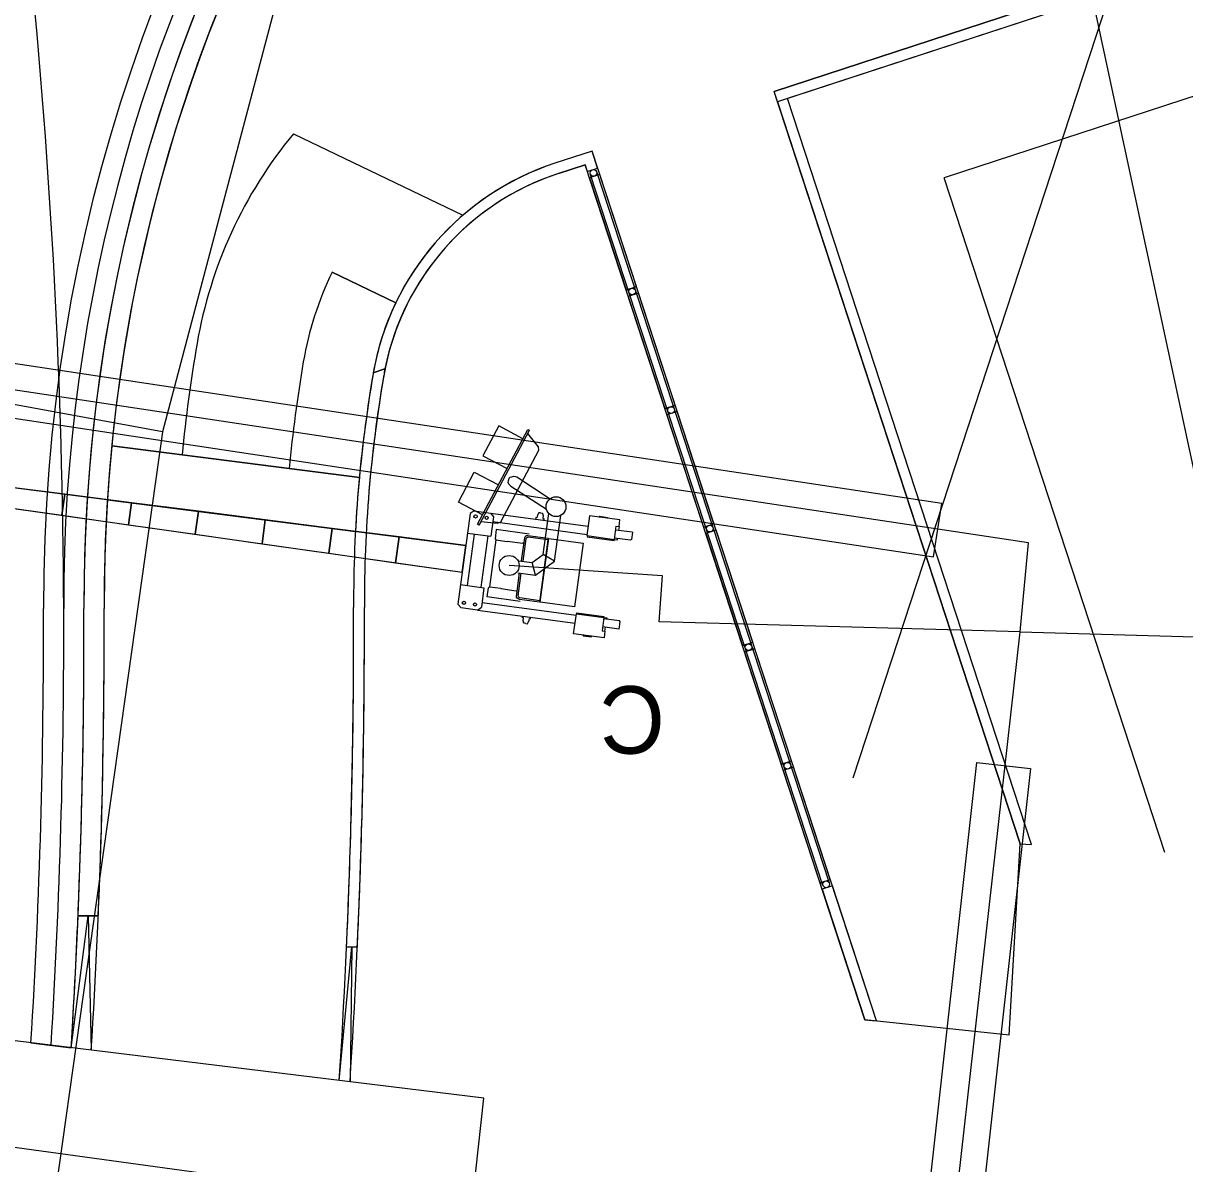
# Model space of a CAD drawing. Extents: x -728802 to -728097, y -1073200 to -1072700.
# Drawn here: x -728502.22 to -728493.61, y -1073043.37 to -1073034.91 of the extents above; entities that cross this region are included whole.
import ezdxf

# ---------------------------------------------------------------- set-up
doc = ezdxf.new("R2010")
doc.units = 0
for name, color, linetype in [('3_třída_přesnosti', 7, 'Continuous'), ('_popis', 7, 'Continuous'), ('Default', 7, 'Continuous'), ('Hranice parcel', 7, 'Continuous'), ('JŽM', 7, 'Continuous'), ('Projekt', 7, 'Continuous'), ('ZZZ_popisky', 7, 'Continuous')]:
    doc.layers.add(name, color=color, linetype=linetype)

# ---------------------------------------------------------------- blocks, each defined once
blk = doc.blocks.new('Závora C_2')
at = {"layer": 'Default'}
for p, q in [((-0.2617, 0.2672), (0.0153, 1.0146)), ((-0.0329, 0.6588), (0.2351, 0.5319)), ((0.6142, 0.4516), (0.6756, 0.4516)), ((0.6756, 0.4516), (0.6756, 0.4453)), ((-0.3118, 0.3667), (-0.338, 0.3428)), ((-0.3118, 0.3667), (-0.1894, 0.3667)), ((-0.1894, 0.3667), (0.541, 0.3667)), ((-0.1894, 0.3667), (-0.1632, 0.3428)), ((0.7691, 0.3953), (0.7691, 0.3666)), ((-0.338, 0.3428), (-0.338, -0.3345)), ((-0.1632, 0.3064), (0.541, 0.3064)), ((-0.338, 0.1967), (-0.1632, 0.1967)), ((-0.288, 0.1967), (-0.288, -0.1884)), ((-0.187, 0.1967), (-0.187, -0.1884)), ((-0.1234, 0.1744), (-0.1234, -0.1756)), ((0.2595, 0.2267), (0.2595, -0.2391)), ((-6.838, 0.0577), (-0.338, 0.1041)), ((-0.338, -0.0959), (-0.338, 0.1041)), ((-0.338, -0.0959), (-0.338, 0.1041)), ((-0.338, -0.0959), (-0.338, 0.1041)), ((-0.338, -0.0959), (-0.338, 0.1041)), ((0.3294, 0.0763), (0.2387, 0.1145)), ((-6.838, -0.0494), (-6.838, 0.0577)), ((0.2022, -0.0454), (0.1648, 0.0444)), ((-6.838, -0.0494), (-0.338, -0.0959)), ((-0.338, -0.1884), (-0.1632, -0.1884)), ((-0.1632, -0.1884), (-0.1632, -0.3345)), ((-0.3118, -0.3584), (-0.338, -0.3345)), ((-0.1894, -0.3584), (-0.1632, -0.3345)), ((-0.1632, -0.2982), (0.5415, -0.2982)), ((-0.1894, -0.3584), (0.5415, -0.3584)), ((0.7691, -0.387), (0.7691, -0.3583)), ((0.6142, -0.4433), (0.6756, -0.4433)), ((0.6756, -0.4433), (0.6756, -0.4371))]:
    blk.add_line(p, q, dxfattribs=at)
for points in [[(-0.025, 0.945), (-0.2143, 1.0151), (-0.3014, 0.7799), (-0.1122, 0.7098)], [(-0.2617, 0.2672), (-0.2744, 0.2719), (0.0025, 1.0193), (0.0153, 1.0146)], [(-0.2511, 0.2958), (-0.1286, 0.2996), (-0.1052, 0.3132), (0.1035, 0.8765), (0.0974, 0.9006), (0.0056, 0.9886)], [(-0.2469, 0.3463), (-0.4361, 0.4164), (-0.349, 0.6516), (-0.1597, 0.5815)], [(-0.0661, 0.5843), (-0.0839, 0.5967), (-0.0888, 0.6096), (-0.0888, 0.625), (-0.0867, 0.641), (-0.0796, 0.6502), (-0.0696, 0.6552), (-0.0549, 0.6602), (-0.0428, 0.6594), (-0.0329, 0.6588)], [(-0.0661, 0.5843), (0.2176, 0.4514)], [(0.5415, 0.4453), (0.5415, 0.2966), (0.7469, 0.2966), (0.7469, 0.3953), (0.7691, 0.3953), (0.7691, 0.4453), (0.5415, 0.4453)], [(0.6142, 0.4516), (0.6142, 0.4453)], [(0.6553, 0.4453), (0.6142, 0.4453)], [(0.0655, 0.0444), (0.1648, 0.0444), (0.2387, 0.1145), (0.2387, 0.4223)], [(0.0712, -0.0454), (0.2022, -0.0454), (0.3294, 0.0763), (0.3294, 0.4195)], [(0.1788, 0.4175), (0.1658, 0.4175), (0.1647, 0.411), (0.1602, 0.4112), (0.1602, 0.4013), (0.1565, 0.4013), (0.1565, 0.3781), (0.1479, 0.3781), (0.1479, 0.3721), (0.1479, 0.3667)], [(0.1788, 0.4175), (0.1919, 0.4175), (0.193, 0.411), (0.1974, 0.4112), (0.1974, 0.4013), (0.2011, 0.4013), (0.2011, 0.3781), (0.2098, 0.3781), (0.2098, 0.3721), (0.2098, 0.3667)], [(0.8722, 0.3666), (0.7469, 0.3666)], [(0.8722, 0.3666), (0.8722, 0.3122), (0.8661, 0.3058), (0.7469, 0.3058)], [(-0.1632, 0.3428), (-0.1632, 0.1967)], [(0.5451, 0.2966), (0.5451, 0.2888), (0.7454, 0.2888), (0.7454, 0.2966)], [(0.7469, 0.2966), (0.7698, 0.2966), (0.7698, 0.3058)], [(0.1158, 0.2513), (-0.1305, 0.2513), (-0.1305, 0.1823), (-0.1234, 0.1744), (-0.0397, 0.1744), (-0.0397, 0.1771), (0.0771, 0.1771), (0.0783, 0.1808), (0.084, 0.1808)], [(0.2595, 0.2379), (0.1085, 0.2379), (0.0984, 0.2356), (0.0919, 0.2296), (0.086, 0.2232), (0.084, 0.2189), (0.084, 0.0454)], [(0.2595, 0.2379), (0.2595, 0.2267), (0.1102, 0.2267), (0.1057, 0.2251), (0.1018, 0.2219), (0.0981, 0.2177), (0.0966, 0.2125), (0.0966, 0.0454)], [(0.265, 0.238), (0.5204, 0.238), (0.5204, -0.2391), (0.265, -0.2391)], [(0.265, -0.2391), (0.265, 0.238)], [(-2.838, -0.078), (-2.838, 0.0863), (-3.338, 0.0827), (-3.338, -0.0744), (-2.838, -0.078)], [(-2.338, -0.0816), (-2.338, 0.0898), (-2.838, 0.0863), (-2.838, -0.078), (-2.338, -0.0816)], [(-1.838, -0.0852), (-1.838, 0.0934), (-2.338, 0.0898), (-2.338, -0.0816), (-1.838, -0.0852)], [(-1.338, -0.0887), (-1.338, 0.097), (-1.838, 0.0934), (-1.838, -0.0852), (-1.338, -0.0887)], [(-0.838, -0.0923), (-0.838, 0.1006), (-1.338, 0.097), (-1.338, -0.0887), (-0.838, -0.0923)], [(-0.338, -0.0959), (-0.338, 0.1041), (-0.838, 0.1006), (-0.838, -0.0923), (-0.338, -0.0959)], [(-6.338, -0.053), (-6.338, 0.0613), (-6.838, 0.0577), (-6.838, -0.0494), (-6.338, -0.053)], [(-5.838, -0.0566), (-5.838, 0.0648), (-6.338, 0.0613), (-6.338, -0.053), (-5.838, -0.0566)], [(-5.338, -0.0602), (-5.338, 0.0684), (-5.838, 0.0648), (-5.838, -0.0566), (-5.338, -0.0602)], [(-4.838, -0.0637), (-4.838, 0.072), (-5.338, 0.0684), (-5.338, -0.0602), (-4.838, -0.0637)], [(-4.338, -0.0673), (-4.338, 0.0756), (-4.838, 0.072), (-4.838, -0.0637), (-4.338, -0.0673)], [(-3.838, -0.0709), (-3.838, 0.0791), (-4.338, 0.0756), (-4.338, -0.0673), (-3.838, -0.0709)], [(-3.338, -0.0744), (-3.338, 0.0827), (-3.838, 0.0791), (-3.838, -0.0709), (-3.338, -0.0744)], [(0.2595, -0.2391), (0.1085, -0.2391), (0.0984, -0.2368), (0.0919, -0.2308), (0.086, -0.2244), (0.084, -0.2201), (0.084, -0.0444)], [(0.2595, -0.2279), (0.1102, -0.2279), (0.1057, -0.2263), (0.1018, -0.2231), (0.0981, -0.2189), (0.0966, -0.2137), (0.0966, -0.0444)], [(0.1158, -0.2525), (-0.1305, -0.2525), (-0.1305, -0.1835), (-0.1234, -0.1756), (-0.0397, -0.1756), (-0.0397, -0.1783), (0.0771, -0.1783), (0.0783, -0.182), (0.084, -0.182)], [(0.5415, -0.4371), (0.5415, -0.2883), (0.7469, -0.2883), (0.7469, -0.387), (0.7691, -0.387), (0.7691, -0.4371), (0.5415, -0.4371)], [(0.5451, -0.2883), (0.5451, -0.2806), (0.7454, -0.2806), (0.7454, -0.2883)], [(0.7469, -0.2883), (0.7698, -0.2883), (0.7698, -0.2975)], [(0.8722, -0.3583), (0.8722, -0.304), (0.8661, -0.2975), (0.7469, -0.2975)], [(-0.1894, -0.3584), (-0.3118, -0.3584)], [(0.1788, -0.4093), (0.1658, -0.4093), (0.1647, -0.4027), (0.1602, -0.403), (0.1602, -0.3931), (0.1565, -0.3931), (0.1565, -0.3698), (0.1479, -0.3698), (0.1479, -0.3639), (0.1479, -0.3584)], [(0.1788, -0.4093), (0.1919, -0.4093), (0.193, -0.4027), (0.1974, -0.403), (0.1974, -0.3931), (0.2011, -0.3931), (0.2011, -0.3698), (0.2098, -0.3698), (0.2098, -0.3639), (0.2098, -0.3584)], [(0.8722, -0.3583), (0.7469, -0.3583)], [(0.6553, -0.4371), (0.6142, -0.4371)], [(0.6142, -0.4433), (0.6142, -0.4371)]]:
    blk.add_lwpolyline(points, dxfattribs=at)
for centre, radius in [((0.2859, 0.4787), 0.0735), ((-0.2961, 0.3274), 0.0119), ((-0.2125, 0.3283), 0.0119), ((0, 0), 0.0742), ((-0.2961, -0.3192), 0.0119), ((-0.2125, -0.3201), 0.0119)]:
    blk.add_circle(centre, radius, dxfattribs=at)

msp = doc.modelspace()

# ---------------------------------------------------------------- linework, layer by layer
at = {"layer": '3_třída_přesnosti'}
for points in [[(-728443.68, -1073014.51), (-728468.68, -1073021.225), (-728493.68, -1073027.94), (-728497.54, -1073030.15), (-728499.78, -1073032.61), (-728501.19, -1073037.94)], [(-728501.19, -1073037.94), (-728510.22, -1073036.28), (-728510.71, -1073032.54), (-728514.39, -1073031.91), (-728543.86, -1073026.9), (-728564.68, -1073020.02)], [(-728501.19, -1073037.94), (-728502.6, -1073047.92), (-728503.24, -1073052.34), (-728496.81, -1073052.21), (-728491.97, -1073053.44), (-728477.97, -1073053.19)]]:
    msp.add_lwpolyline(points, dxfattribs=at)
at = {"layer": '_popis'}
msp.add_lwpolyline([(-728100, -1073009.894), (-728187.9598, -1073038.5344), (-728349.393, -1073048.7368), (-728486.1864, -1073072.5424), (-728495.9685, -1073026.8944)], dxfattribs=at)
at = {"layer": 'Hranice parcel'}
msp.add_circle((-728505.883, -1073042.015), 62.4806, dxfattribs=at)
at = {"layer": 'JŽM'}
for points in [[(-728320.8, -1073026.914), (-728374.008, -1073033.722), (-728429.095, -1073040.747), (-728461.932, -1073044.273), (-728481.199, -1073044.815), (-728499.353, -1073043.648), (-728506.01, -1073042.737), (-728514.574, -1073041.329), (-728535.848, -1073035.998), (-728561.353, -1073026.113), (-728583.963, -1073013.524), (-728603.757, -1072998.891), (-728619.185, -1072984.418), (-728634.193, -1072966.825), (-728646.078, -1072949.194), (-728656.182, -1072930.072), (-728664.987, -1072910.227)], [(-728514.104, -1073040.67), (-728514.376, -1073042.064), (-728513.93, -1073042.165), (-728506.122, -1073043.424), (-728499.477, -1073044.316), (-728498.964, -1073044.302), (-728498.807, -1073042.881), (-728505.883, -1073042.015), (-728513.61, -1073040.728), (-728514.104, -1073040.67)]]:
    msp.add_lwpolyline(points, dxfattribs=at)
at = {"layer": 'Projekt'}
for p, q in [((-728494.83, -1073040.995), (-728496.6548, -1073035.4168)), ((-728494.7442, -1073041.0001), (-728496.5539, -1073035.4679)), ((-728500.2193, -1073035.7295), (-728498.9627, -1073036.3337)), ((-728498.0044, -1073035.8583), (-728498.2793, -1073035.9482)), ((-728497.9635, -1073035.9835), (-728498.0044, -1073035.8583)), ((-728495.8946, -1073042.3079), (-728498.0044, -1073035.8583)), ((-728498.2544, -1073036.0242), (-728498.0556, -1073035.9592)), ((-728498.0556, -1073035.9592), (-728498.0395, -1073036.0084)), ((-728495.9818, -1073042.2985), (-728498.0556, -1073035.9592)), ((-728498.0395, -1073036.0084), (-728497.9635, -1073035.9835)), ((-728497.9796, -1073036.0414), (-728498.024, -1073036.0559)), ((-728498.024, -1073036.0559), (-728497.7519, -1073036.8875)), ((-728496.2919, -1073041.3024), (-728498.0175, -1073036.0275)), ((-728497.9479, -1073036.031), (-728497.9796, -1073036.0414)), ((-728496.2444, -1073041.2869), (-728497.97, -1073036.0119)), ((-728497.6759, -1073036.8627), (-728497.9479, -1073036.031)), ((-728493.7572, -1073041.0582), (-728495.3935, -1073036.0563)), ((-728499.933, -1073036.7548), (-728499.4599, -1073036.9823)), ((-728497.7519, -1073036.8875), (-728497.6759, -1073036.8627)), ((-728497.6603, -1073036.9102), (-728497.7364, -1073036.9351)), ((-728497.7364, -1073036.9351), (-728497.4643, -1073037.7667)), ((-728497.3883, -1073037.7418), (-728497.6603, -1073036.9102)), ((-728499.6269, -1073037.5009), (-728499.5402, -1073037.4725)), ((-728499.5402, -1073037.4725), (-728499.6269, -1073037.5009)), ((-728497.4643, -1073037.7667), (-728497.3883, -1073037.7418)), ((-728497.3727, -1073037.7893), (-728497.4488, -1073037.8142)), ((-728497.4488, -1073037.8142), (-728497.1767, -1073038.6458)), ((-728497.1007, -1073038.621), (-728497.3727, -1073037.7893)), ((-728501.5662, -1073038.0437), (-728499.7302, -1073038.2783)), ((-728501.5987, -1073038.4428), (-728499.7594, -1073038.6778)), ((-728501.5987, -1073038.4428), (-728499.7594, -1073038.6778)), ((-728497.1767, -1073038.6458), (-728497.1324, -1073038.6313)), ((-728497.1238, -1073038.6811), (-728497.1612, -1073038.6934)), ((-728497.1324, -1073038.6313), (-728497.1007, -1073038.621)), ((-728497.0851, -1073038.6685), (-728497.1238, -1073038.6811)), ((-728496.8131, -1073039.5001), (-728497.0851, -1073038.6685)), ((-728497.1612, -1073038.6934), (-728496.8891, -1073039.525)), ((-728499.7732, -1073039.2419), (-728499.7732, -1073039.2419)), ((-728496.8891, -1073039.525), (-728496.8131, -1073039.5001)), ((-728496.7975, -1073039.5476), (-728496.8736, -1073039.5725)), ((-728496.8736, -1073039.5725), (-728496.6015, -1073040.4041)), ((-728496.5255, -1073040.3793), (-728496.7975, -1073039.5476)), ((-728496.6015, -1073040.4041), (-728496.5255, -1073040.3793)), ((-728496.5099, -1073040.4268), (-728496.586, -1073040.4517)), ((-728496.586, -1073040.4517), (-728496.3139, -1073041.2833)), ((-728496.2379, -1073041.2584), (-728496.5099, -1073040.4268)), ((-728494.91, -1073042.414), (-728494.83, -1073040.995)), ((-728496.3139, -1073041.2833), (-728496.2379, -1073041.2584)), ((-728496.2223, -1073041.3059), (-728496.2984, -1073041.3308)), ((-728496.2984, -1073041.3308), (-728495.9818, -1073042.2985)), ((-728495.8946, -1073042.3079), (-728496.2223, -1073041.3059)), ((-728501.8676, -1073042.5064), (-728501.7419, -1073041.5296)), ((-728501.8169, -1073041.5296), (-728501.6668, -1073041.5296)), ((-728501.7419, -1073041.5296), (-728501.7184, -1073042.5247)), ((-728499.8789, -1073042.7498), (-728499.785, -1073041.7592)), ((-728499.825, -1073041.7574), (-728499.785, -1073041.7592)), ((-728499.745, -1073041.761), (-728499.825, -1073041.7574)), ((-728499.785, -1073041.7592), (-728499.7994, -1073042.7595)), ((-728499.785, -1073041.7592), (-728499.745, -1073041.761)), ((-728495.9818, -1073042.2985), (-728495.8946, -1073042.3079)), ((-728494.91, -1073042.414), (-728495.9818, -1073042.2985))]:
    msp.add_line(p, q, dxfattribs=at)
for points in [[(-728488.1311, -1073032.6284), (-728496.6548, -1073035.4168)], [(-728488.1062, -1073032.7044), (-728496.6299, -1073035.4928)], [(-728496.6548, -1073035.4168), (-728491.3522, -1073033.6821), (-728490.5897, -1073033.4327), (-728489.0615, -1073032.9328), (-728488.9853, -1073032.9078), (-728488.6063, -1073032.7839), (-728488.5939, -1073032.8219), (-728488.5814, -1073032.8599), (-728496.5539, -1073035.4679), (-728496.6299, -1073035.4928), (-728496.6548, -1073035.4168), (-728496.6548, -1073035.4168)], [(-728487.8202, -1073033.5788), (-728495.3935, -1073036.0563)], [(-728494.83, -1073040.995), (-728494.7442, -1073041.0001), (-728496.5539, -1073035.4679), (-728496.6299, -1073035.4928), (-728494.83, -1073040.995), (-728494.83, -1073040.995)], [(-728495.4708, -1073038.866), (-728495.4112, -1073038.4705), (-728513.1672, -1073035.794), (-728513.2268, -1073036.1895), (-728495.4708, -1073038.866)], [(-728494.8293, -1073039.4222), (-728494.7672, -1073038.7637), (-728513.9156, -1073035.8794)], [(-728498.0044, -1073035.8583), (-728498.2793, -1073035.9482)], [(-728498.0556, -1073035.9592), (-728498.2544, -1073036.0242)], [(-728499.4599, -1073036.9823), (-728499.933, -1073036.7548)], [(-728494.8293, -1073039.4222), (-728493.8801, -1073039.4503), (-728491.2923, -1073039.5248), (-728491.1915, -1073036.939)], [(-728499.7302, -1073038.2783), (-728500.2513, -1073038.2117), (-728501.0452, -1073038.1102), (-728501.5662, -1073038.0437)], [(-728500.2513, -1073038.2117), (-728499.7302, -1073038.2783), (-728499.7302, -1073038.2783)], [(-728494.8293, -1073039.4225), (-728497.5063, -1073039.348), (-728497.4824, -1073039.0081), (-728498.619, -1073038.9309)], [(-728499.6877, -1073048.4364), (-728495.793, -1073047.9948), (-728494.8293, -1073039.4222)], [(-728495.5261, -1073047.3929), (-728495.9236, -1073047.3487), (-728495.1506, -1073040.3916), (-728494.753, -1073040.4357), (-728495.5261, -1073047.3929)], [(-728501.6668, -1073041.5296), (-728501.7419, -1073041.5296), (-728501.8169, -1073041.5296)], [(-728501.8676, -1073042.5064), (-728502.1659, -1073042.4699)], [(-728502.1659, -1073042.4699), (-728501.8676, -1073042.5064)]]:
    msp.add_lwpolyline(points, dxfattribs=at)
for centre in [(-728497.9937, -1073036.0197), (-728497.7061, -1073036.8989), (-728497.4185, -1073037.778), (-728497.1309, -1073038.6572), (-728496.8433, -1073039.5363), (-728496.5557, -1073040.4155), (-728496.2681, -1073041.2946)]:
    msp.add_circle(centre, 0.025, dxfattribs=at)
for centre, radius, start, end in [((-728489.7733, -1073039.2055), 12.3, 105.42005, 180.20859), ((-728489.7733, -1073039.2055), 12.3, 105.42005, 180.20859), ((-728489.7733, -1073039.2055), 12, 105.42005, 180.20859), ((-728489.7733, -1073039.2055), 11.85, 105.42005, 180.20859), ((-728489.7733, -1073039.2055), 12.15, 116.96186, 180.20859), ((-728489.7733, -1073039.2055), 12, 121.87344, 180.20859), ((-728489.7733, -1073039.2055), 12, 121.87344, 180.20859), ((-728489.7733, -1073039.2055), 11.85, 121.87344, 180.20859), ((-728551.7729, -1073039.4312), 49.85, 0.20866, 11.41452), ((-728497.6575, -1073037.8491), 3.325, 140.39567, 170.238), ((-728497.6575, -1073037.8491), 2, 108.11454, 170.238), ((-728497.6575, -1073037.8491), 2, 108.11454, 169.97457), ((-728497.6575, -1073037.8491), 1.92, 108.11454, 170.238), ((-728497.6575, -1073037.8491), 1.92, 108.11454, 168.6899), ((-728497.6575, -1073037.8491), 2.525, 154.31772, 170.238), ((-728497.6575, -1073037.8491), 2.525, 154.31772, 170.238), ((-728497.6575, -1073037.8491), 2, 154.31772, 170.238), ((-728489.7733, -1073039.2055), 11.325, 170.238, 174.45004), ((-728489.7733, -1073039.2055), 10.525, 170.238, 174.58167), ((-728489.7733, -1073039.2055), 10.525, 170.238, 174.58167), ((-728497.6575, -1073037.8491), 1.92, 168.6899, 170.238), ((-728489.7733, -1073039.2055), 10, 170.238, 180.20856), ((-728489.7733, -1073039.2055), 10, 170.238, 180.20859), ((-728489.7733, -1073039.2055), 10, 170.238, 174.6795), ((-728489.7733, -1073039.2055), 9.92, 170.238, 180.20859), ((-728489.7733, -1073039.2055), 9.92, 170.26724, 180.20859), ((-728497.6575, -1073037.8491), 2, 169.97457, 170.23799), ((-728489.7767, -1073039.205), 9.9166, 170.23799, 170.26724), ((-728489.7733, -1073039.2055), 11.85, 174.37332, 176.30947), ((-728489.7733, -1073039.2055), 10, 174.6795, 176.97486), ((-728551.7729, -1073039.4312), 49.7, 356.49472, 0.20859), ((-728551.7729, -1073039.4312), 49.7, 356.49472, 0.20859), ((-728551.7729, -1073039.4312), 49.85, 356.48426, 0.20859), ((-728551.7729, -1073039.4312), 50, 356.47386, 0.20859), ((-728551.7729, -1073039.4312), 50, 357.5948, 0.20859), ((-728551.7729, -1073039.4312), 50, 357.5948, 0.20859), ((-728551.7729, -1073039.4312), 50.15, 356.46353, 0.20859), ((-728551.7729, -1073039.4312), 50.15, 357.602, 0.20859), ((-728551.7729, -1073039.4312), 52, 356.34097, 0.20859), ((-728551.7729, -1073039.4312), 52.08, 356.33586, 0.20859), ((-728551.7729, -1073039.4312), 52, 359.92959, 0.20859), ((-728551.7729, -1073039.4312), 52.08, 359.95849, 0.20859), ((-728551.7725, -1073039.4312), 51.9996, 359.87159, 359.92959), ((-728551.7729, -1073039.4312), 52.08, 358.88417, 359.9006), ((-728551.7727, -1073039.4312), 52.0798, 359.9006, 359.95849), ((-728551.7729, -1073039.4312), 52, 358.85342, 359.87159), ((-728551.7732, -1073039.4312), 52.0004, 358.79505, 358.85342), ((-728551.7727, -1073039.4312), 52.0798, 358.8259, 358.88417), ((-728551.7729, -1073039.4312), 52, 357.77014, 358.79505), ((-728551.7729, -1073039.4312), 52.08, 357.80277, 358.8259), ((-728551.7726, -1073039.4313), 52.0797, 357.7441, 357.80277), ((-728551.7729, -1073039.4312), 52, 357.43603, 357.71137), ((-728551.7731, -1073039.4312), 52.0002, 357.71137, 357.77014), ((-728551.7729, -1073039.4312), 52.08, 357.43603, 357.7441), ((-728551.7729, -1073039.4312), 50, 356.47386, 357.5948)]:
    msp.add_arc(centre, radius, start, end, dxfattribs=at)
at = {"layer": 'ZZZ_popisky'}
msp.add_lwpolyline([(-728496.0689, -1073040.506), (-728413.2179, -1072787.6343), (-728463.1083, -1072771.2882)], dxfattribs=at)

# ---------------------------------------------------------------- block references
at = {"layer": 'Projekt', "rotation": -7.690384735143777}
msp.add_blockref('Závora C_2', (-728498.619, -1073038.9309), dxfattribs=at)

# ---------------------------------------------------------------- texts
at = {"layer": 'Projekt'}
msp.add_text('C', height=0.5, rotation=180, dxfattribs=at).set_placement((-728497.4635, -1073039.8255))

doc.saveas('drawing.dxf')
